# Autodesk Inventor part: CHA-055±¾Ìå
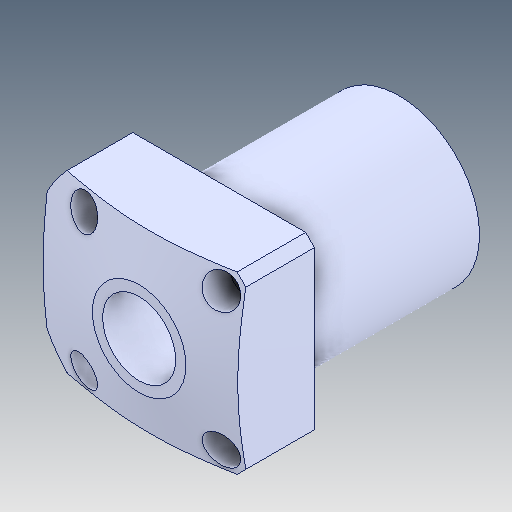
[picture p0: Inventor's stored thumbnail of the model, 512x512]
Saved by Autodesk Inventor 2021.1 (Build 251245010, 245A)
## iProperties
Created: 2021-05
Part Number: CHA-055±¾Ìå
Material: Ogólny
Document SubType Name: Modeling
Designer: user
Density: 1 g/cm^3
Appearance: Domyślna
Author: user
Revision Number: ÈÎºÎ
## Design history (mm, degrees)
feature "µ¹½Ç1"
node "Bryła1"
